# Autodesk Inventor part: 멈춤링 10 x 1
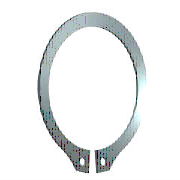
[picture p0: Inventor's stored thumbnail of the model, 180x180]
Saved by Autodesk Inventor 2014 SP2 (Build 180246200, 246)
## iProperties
IsCustomPart: 0
Created: 2015-11
Part Number: 멈춤링 10 x 1
Material: 스테인리스강
Description: 리테이닝 링(C형)
Document SubType Name: Modeling
Standard: KS B 1336
Designer: mdu
Standards Organization: KS
Language: ko-KR
Size Designation: 10 x 1
Categories: <MemberInstance><Categories><Category DisplayName="샤프트 부품" InternalName="7f7aeb1f-a693-4053-b835-cee3144e0d98" Mnemonic="SHFT"><Category DisplayName="써클립" Inter
Density: 1 g/cm^3
Appearance: 반광택
Author: mdu
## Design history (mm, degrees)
sketch "스케치1"
  geometry: L1 (-6, 0)-(6, 0) reference; L2 (0, 20.189)-(0, -80.536) reference; L3 (-48.09, 0)-(48.09, 0) reference; L4 (-0.3, -9.791)-(-0.3, -12.791); L5 (-0.3, -6.54)-(-0.3, -13.29); L6 (-2.795, 1.6)-(3.672, 1.6); L7 (0.3, -6.54)-(0.3, -13.29); L8 (0.3, -9.791)-(0.3, -12.791); C1 r 0.6 at (-1.2, -11.486); C2 r 0.6 at (1.2, -11.486); A1 r 4.8 centre (0, -5) between (0.3, -9.791) and (-0.3, -9.791); A2 r 6.2 centre (0, -4.6) between (2.988, -10.033) and (-2.988, -10.033); A3 r 7.796 centre (0, -5) between (-1.418, -12.666) and (-0.3, -12.791); A4 r 1.2 centre (-1.2, -11.486) between (-2.383, -11.285) and (-1.418, -12.666); A5 r 1.2 centre (-3.566, -11.084) between (-2.383, -11.285) and (-2.988, -10.033); A6 r 1.2 centre (3.566, -11.084) between (2.988, -10.033) and (2.383, -11.285); A7 r 1.2 centre (1.2, -11.486) between (1.418, -12.666) and (2.383, -11.285); A8 r 7.796 centre (0, -5) between (0.3, -12.791) and (1.418, -12.666)
  constraints: 16 point on circle, 12 end point, 10 centre point, 9 symmetric about line, 5 point on line, 4 tangent, 3 coincident, 2 horizontal, 1 perpendicular, 1 vertical, 5 other
  dimensions: "d0" = 9.6 diameter of A1 (= ND); "d1" = 3 distance of L4.end L4.start (= SRB2); "d6" = 0.3 distance between parallel lines of L2 L5 (= 0.25 x SD5); "d7" = 1.6 distance between parallel lines of L6 L3 (= SRB1); "d8" = 0.4 distance of A1.centre A2.centre (= 0.25 x SRB1); "d9" = 1.2 radius of A4 (= SD5); "d10" = 1.2 radius of A5 (= SD5); "d11" = 0.9 distance from line of L4 A4.centre (= 0.75 x SD5); "d12" = 1.2 diameter of C1 (= SD5); "d13" = 1.2 diameter of C2 (= SD5); "d14" = 5 distance from line of A1.centre L1 (= 0.5 x WD)
extrude "본체" new body sketch "스케치1" distance "d2" = 1 (= SD); taper "d3" = 0 deg
workaxis "Work Axis1"
workplane "Work Plane1"
body "Solid1"
other parameters: "SD" = 1 [user parameter; used in 1 equation term], "SRB1" = 1.6 [user parameter; used in 2 equation terms], "ND" = 9.6 [user parameter; used in 1 equation term], "SRB2" = 3 [user parameter; used in 1 equation term], "SD5" = 1.2 [user parameter; used in 6 equation terms], "d15" = 0, "d16" = 0, "d17" = 0, "d41" = 0, "d42" = 0, "SD3" = 9.3 [user parameter], "WDMAX" = 11 [user parameter]
